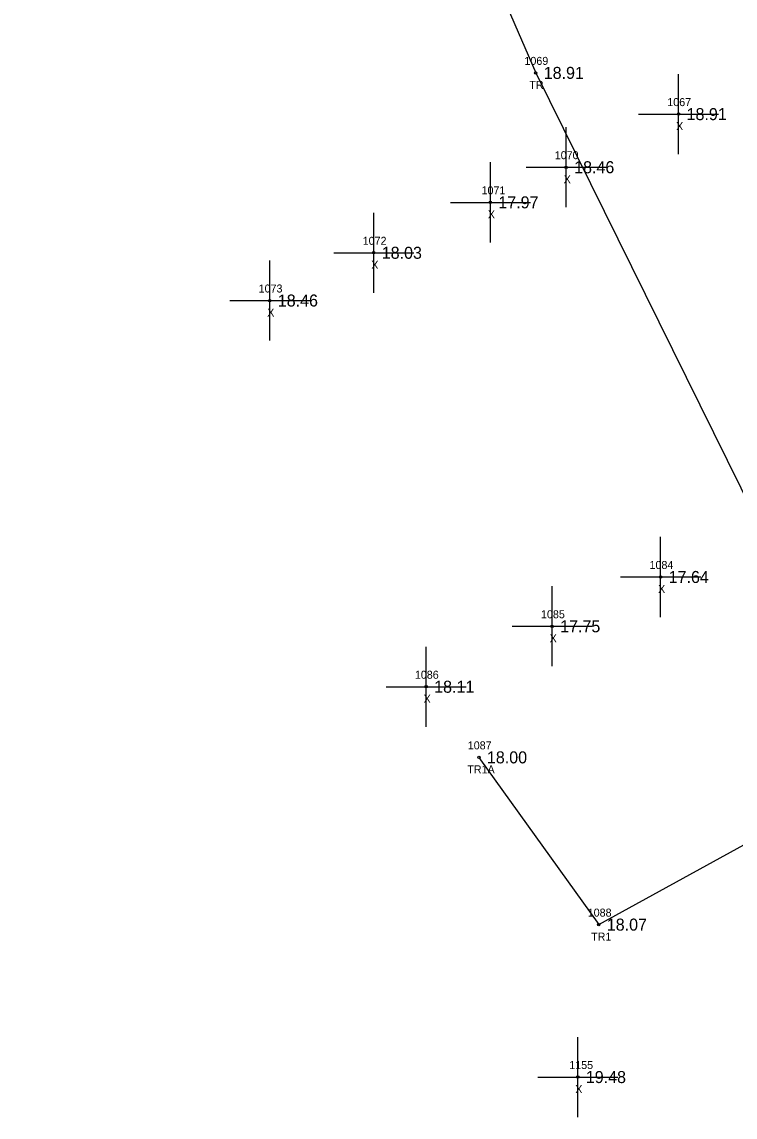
# Model space of a CAD drawing. Extents: x 2042211 to 2045853, y 303080 to 309569.
# Drawn here: x 2042864.3 to 2042953.4, y 306464.5 to 306601.3 of the extents above; entities that cross this region are included whole.
import ezdxf

# ---------------------------------------------------------------- set-up
doc = ezdxf.new("R2010")
doc.units = 0
for name, color, linetype in [('BR_500YR_SCOUR', 7, 'Continuous'), ('RD_EX_Misc', 7, 'Continuous'), ('RD_EX_Misc_txCode', 7, 'Continuous'), ('RD_EX_TX_Misc_ELEV', 7, 'Continuous'), ('RD_EX_TX_VEG_ELEV', 7, 'Continuous'), ('RD_EX_VEG_txCode', 7, 'Continuous'), ('RD_SMD_Locator', 7, 'Continuous')]:
    doc.layers.add(name, color=color, linetype=linetype)

msp = doc.modelspace()

# ---------------------------------------------------------------- linework, layer by layer
at = {"layer": 'BR_500YR_SCOUR'}
for points in [[(2042864.25, 306612.56), (2042883.28, 306667.35), (2042906.08, 306641.46), (2042916.37, 306622.92), (2042928.46, 306594.97), (2042955.8, 306539.7), (2042967.97, 306505.97)], [(2042921.36, 306509.48), (2042936.34, 306488.59), (2042967.97, 306505.97)]]:
    msp.add_lwpolyline(points, dxfattribs=at)
for centre in [(2042928.46, 306594.97), (2042921.36, 306509.48), (2042936.34, 306488.59)]:
    msp.add_circle(centre, 0.15, dxfattribs=at)
at = {"layer": 'RD_EX_Misc'}
for p, q in [((2042946.31, 306584.82), (2042946.31, 306594.82)), ((2042941.31, 306589.82), (2042951.31, 306589.82)), ((2042932.26, 306578.19), (2042932.26, 306588.19)), ((2042922.79, 306573.8), (2042922.79, 306583.8)), ((2042927.26, 306583.19), (2042937.26, 306583.19)), ((2042917.79, 306578.8), (2042927.79, 306578.8)), ((2042908.22, 306567.5), (2042908.22, 306577.5)), ((2042895.23, 306561.54), (2042895.23, 306571.54)), ((2042903.22, 306572.5), (2042913.22, 306572.5)), ((2042890.23, 306566.54), (2042900.23, 306566.54)), ((2042944.07, 306527.01), (2042944.07, 306537.01)), ((2042939.07, 306532.01), (2042949.07, 306532.01)), ((2042930.51, 306520.85), (2042930.51, 306530.85)), ((2042925.51, 306525.85), (2042935.51, 306525.85)), ((2042914.77, 306513.3), (2042914.77, 306523.3)), ((2042909.77, 306518.3), (2042919.77, 306518.3)), ((2042933.72, 306464.55), (2042933.72, 306474.55)), ((2042928.72, 306469.55), (2042938.72, 306469.55))]:
    msp.add_line(p, q, dxfattribs=at)
at = {"layer": 'RD_SMD_Locator'}
for centre in [(2042946.31, 306589.82), (2042932.26, 306583.19), (2042922.79, 306578.8), (2042908.22, 306572.5), (2042895.23, 306566.54), (2042944.07, 306532.01), (2042930.51, 306525.85), (2042914.77, 306518.3), (2042933.72, 306469.55)]:
    msp.add_circle(centre, 0.15, dxfattribs=at)

# ---------------------------------------------------------------- texts
at = {"layer": 'RD_EX_Misc_txCode'}
for s, p in [('1067', (2042944.9, 306590.82)), ('X', (2042946, 306587.82)), ('1070', (2042930.84, 306584.19)), ('X', (2042931.95, 306581.19)), ('1071', (2042921.69, 306579.8)), ('X', (2042922.48, 306576.8)), ('1072', (2042906.84, 306573.5)), ('X', (2042907.91, 306570.5)), ('1073', (2042893.84, 306567.54)), ('X', (2042894.91, 306564.54)), ('1084', (2042942.68, 306533.01)), ('X', (2042943.75, 306530.01)), ('1085', (2042929.12, 306526.85)), ('X', (2042930.2, 306523.85)), ('1086', (2042913.36, 306519.3)), ('X', (2042914.45, 306516.3)), ('1155', (2042932.65, 306470.55)), ('X', (2042933.4, 306467.55))]:
    msp.add_text(s, height=1, dxfattribs=at).set_placement(p)
at = {"layer": 'RD_EX_TX_Misc_ELEV'}
for s, p in [('18.91', (2042947.31, 306589.07)), ('18.46', (2042933.26, 306582.44)), ('17.97', (2042923.79, 306578.05)), ('18.03', (2042909.22, 306571.75)), ('18.46', (2042896.23, 306565.79)), ('17.64', (2042945.07, 306531.26)), ('17.75', (2042931.51, 306525.1)), ('18.11', (2042915.77, 306517.55)), ('19.48', (2042934.72, 306468.8))]:
    msp.add_text(s, height=1.5, dxfattribs=at).set_placement(p)
at = {"layer": 'RD_EX_TX_VEG_ELEV'}
for s, p in [('18.91', (2042929.46, 306594.22)), ('18.00', (2042922.36, 306508.73)), ('18.07', (2042937.34, 306487.84))]:
    msp.add_text(s, height=1.5, dxfattribs=at).set_placement(p)
at = {"layer": 'RD_EX_VEG_txCode'}
for s, p in [('1069', (2042927.05, 306595.97)), ('TR', (2042927.66, 306592.97)), ('1087', (2042919.97, 306510.48)), ('TR1A', (2042919.91, 306507.48)), ('1088', (2042934.96, 306489.59)), ('TR1', (2042935.38, 306486.59))]:
    msp.add_text(s, height=1, dxfattribs=at).set_placement(p)

doc.saveas('drawing.dxf')
